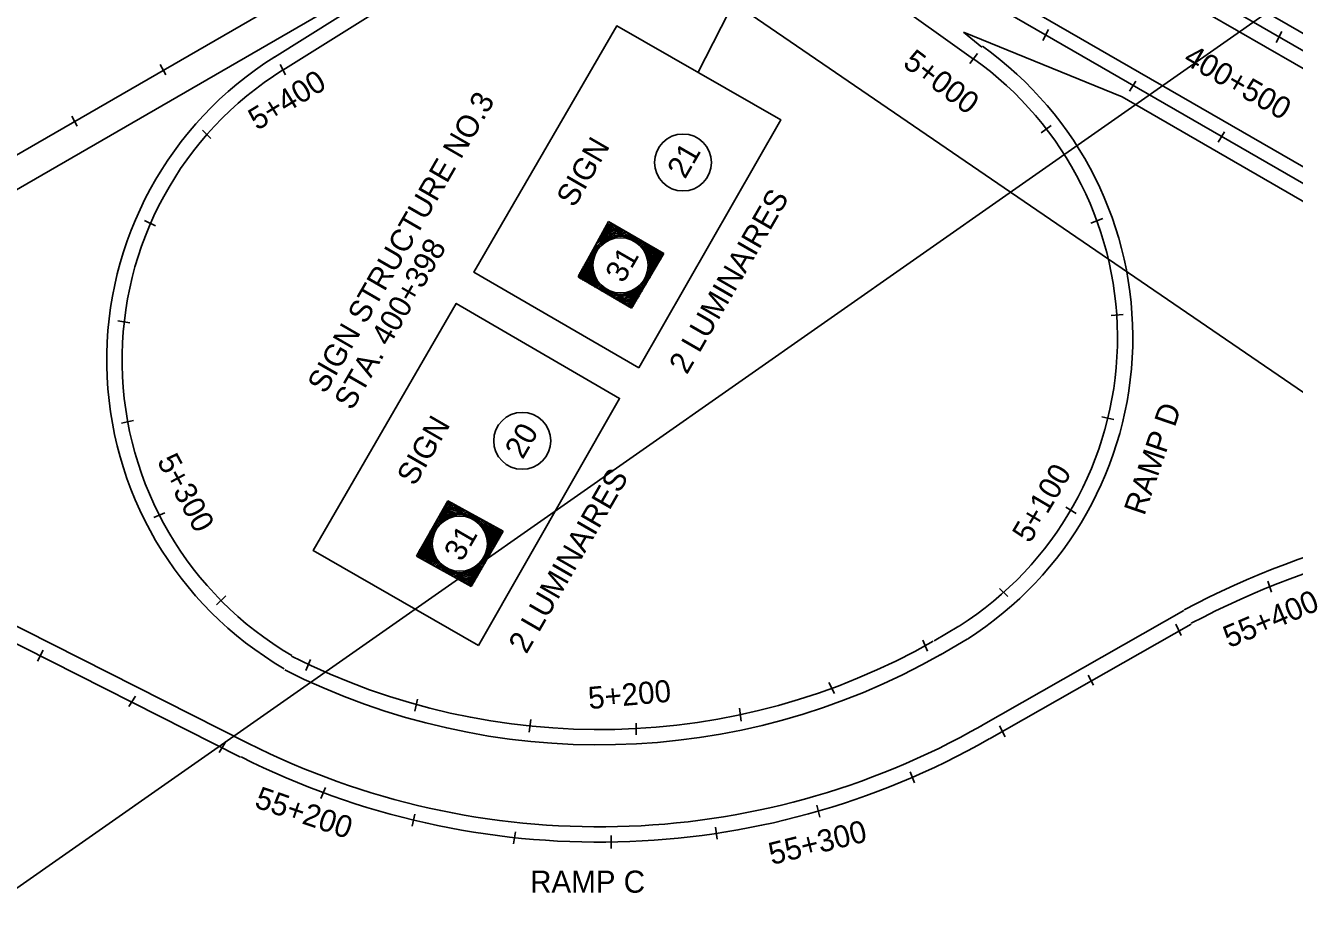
# Model space of a CAD drawing. Extents: x 36 to 2622, y -5330 to 219.
# Drawn here: x 2003.5 to 2175.5, y -4537.5 to -4415.8 of the extents above; entities that cross this region are included whole.
import ezdxf

# ---------------------------------------------------------------- set-up
doc = ezdxf.new("R2010")
doc.units = 0
doc.layers.add('2', color=7, linetype='Continuous')

msp = doc.modelspace()

# ---------------------------------------------------------------- linework, layer by layer
at = {"layer": '2'}
for p, q in [((2538.01, -4157.41), (1748.46, -4710.54)), ((1732.85, -4161.87), (2538.01, -4712.77)), ((1962.23, -4456.45), (2237.61, -4297.45)), ((2381.86, -4540.2), (2110.36, -4383.33)), ((2382.98, -4538.33), (2117.11, -4384.83)), ((2375.11, -4551.83), (2096.98, -4391.2)), ((2376.11, -4550.08), (2099.11, -4390.2)), ((2131.98, -4420.33), (2093.48, -4392.83)), ((2038.36, -4421.83), (2080.86, -4395.2)), ((2094.61, -4422.2), (2108.73, -4394.33)), ((2141.73, -4396.7), (2268.36, -4469.83)), ((1964.36, -4459.95), (2068.36, -4399.83)), ((2037.23, -4420.08), (2068.61, -4400.33)), ((2152.11, -4425.45), (2130.61, -4416.7)), ((2133.11, -4418.7), (2130.61, -4416.7)), ((2141.36, -4417.83), (2142.11, -4416.33)), ((2172.98, -4418.08), (2173.73, -4416.58)), ((2022.48, -4422.45), (2021.73, -4421.08)), ((2038.73, -4422.45), (2037.98, -4421.08)), ((2131.48, -4420.95), (2132.48, -4419.58)), ((2153.11, -4424.7), (2153.98, -4423.33)), ((2274.11, -4495.95), (2152.11, -4425.45)), ((2010.48, -4429.45), (2009.73, -4428.08)), ((2141.11, -4430.33), (2142.48, -4429.33)), ((2028.61, -4431.08), (2027.48, -4429.95)), ((2165.11, -4431.58), (2165.98, -4430.2)), ((2021.11, -4442.95), (2019.61, -4442.2)), ((2147.86, -4442.58), (2149.48, -4441.95)), ((2152.23, -4454.95), (2150.61, -4455.08)), ((2015.98, -4455.83), (2017.61, -4456.08)), ((2149.36, -4468.83), (2150.98, -4469.2)), ((2018.11, -4469.33), (2016.48, -4469.7)), ((2145.86, -4481.95), (2144.48, -4481.08)), ((2020.86, -4482.45), (2022.36, -4481.83)), ((2171.86, -4491.08), (2172.36, -4492.58)), ((2033.61, -4513.08), (1993.11, -4492.58)), ((2030.61, -4493.08), (2029.36, -4494.33)), ((2135.48, -4492.08), (2136.61, -4493.2)), ((2032.61, -4514.95), (1992.11, -4494.45)), ((2132.98, -4510.7), (2160.48, -4495.08)), ((2129.98, -4497.2), (2126.61, -4499.2)), ((2134.11, -4512.45), (2161.48, -4496.95)), ((2159.36, -4496.95), (2160.11, -4498.45)), ((2125.11, -4499.08), (2125.73, -4500.58)), ((2131.11, -4498.95), (2127.48, -4501.08)), ((2005.11, -4501.95), (2005.86, -4500.45)), ((2041.48, -4503.2), (2042.11, -4501.7)), ((2112.36, -4504.83), (2113.11, -4506.33)), ((2147.48, -4503.83), (2148.23, -4505.2)), ((2017.48, -4508.08), (2018.36, -4506.7)), ((2056.61, -4507.08), (2056.23, -4508.7)), ((2100.23, -4508.33), (2100.48, -4510.08)), ((2071.98, -4509.83), (2071.73, -4511.58)), ((2086.23, -4510.33), (2086.23, -4511.95)), ((2135.48, -4510.7), (2136.23, -4512.2)), ((2029.73, -4514.33), (2030.61, -4512.83)), ((2123.36, -4516.95), (2123.98, -4518.45)), ((2044.11, -4519.08), (2043.48, -4520.58)), ((2110.73, -4521.45), (2111.11, -4523.08)), ((2056.23, -4522.7), (2055.86, -4524.33)), ((2069.86, -4525.08), (2069.61, -4526.7)), ((2082.86, -4525.58), (2082.86, -4527.33)), ((2096.98, -4524.45), (2097.23, -4526.08))]:
    msp.add_line(p, q, dxfattribs=at)
for points in [[(2086.61, -4462.2), (2105.86, -4428.58), (2083.61, -4415.83), (2064.23, -4449.2)], [(2064.86, -4499.83), (2083.98, -4466.33), (2061.86, -4453.45), (2042.48, -4486.95)]]:
    msp.add_lwpolyline(points, close=True, dxfattribs=at)
for points in [[(2082.48, -4442.33), (2078.36, -4449.83)], [(2089.98, -4446.7), (2082.48, -4442.33)], [(2089.98, -4446.7), (2085.61, -4454.08)], [(2085.61, -4454.08), (2078.36, -4449.83)], [(2060.73, -4480.2), (2056.48, -4487.7)], [(2068.23, -4484.33), (2060.73, -4480.2)], [(2068.23, -4484.33), (2063.86, -4491.83)], [(2063.86, -4491.83), (2056.48, -4487.7)]]:
    msp.add_lwpolyline(points, dxfattribs=at)
for centre, radius in [((2092.58, -4434.35), 3.86), ((2084.12, -4448.29), 4.13), ((2084.12, -4448.29), 3.95), ((2084.12, -4448.29), 3.74), ((2070.79, -4472.08), 3.86), ((2062.33, -4486.02), 4.13), ((2062.33, -4486.02), 3.95), ((2062.33, -4486.02), 3.74)]:
    msp.add_circle(centre, radius, dxfattribs=at)
for centre, radius, start, end in [((2105.11, -4458.09), 48.44, 302.5087, 54.6076), ((2062.92, -4461.12), 48.44, 121.9999, 239.7607), ((2105.11, -4458.09), 46.36, 302.5087, 54.6076), ((2062.92, -4461.12), 46.36, 121.9999, 239.7607), ((2084.12, -4448.29), 4.89, 88.6036, 121.5088), ((2084.12, -4448.29), 5.06, 92.1022, 117.9954), ((2084.12, -4448.29), 5.26, 95.3377, 114.7487), ((2084.12, -4448.29), 5.45, 98.0414, 112.0368), ((2084.12, -4448.29), 5.62, 100.231, 109.8414), ((2084.12, -4448.29), 5.8, 102.2801, 107.7872), ((2084.12, -4448.29), 4.32, 66.9038, 143.621), ((2084.12, -4448.29), 4.53, 78.7747, 131.406), ((2084.12, -4448.29), 4.73, 84.969, 125.1626), ((2084.12, -4448.29), 4.32, 336.9038, 53.0962), ((2084.12, -4448.29), 4.32, 156.379, 233.621), ((2084.12, -4448.29), 4.53, 348.7747, 41.2253), ((2084.12, -4448.29), 4.73, 354.969, 35.031), ((2084.12, -4448.29), 4.89, 358.6036, 31.3964), ((2084.12, -4448.29), 5.06, 2.1022, 27.8978), ((2084.12, -4448.29), 5.26, 5.3377, 24.6623), ((2084.12, -4448.29), 5.45, 8.0414, 21.9586), ((2084.12, -4448.29), 5.62, 10.231, 19.769), ((2084.12, -4448.29), 5.8, 12.2801, 17.7199), ((2084.12, -4448.29), 5.06, 182.0046, 207.9954), ((2084.12, -4448.29), 4.89, 178.4912, 211.5088), ((2084.12, -4448.29), 4.73, 174.8374, 215.1626), ((2084.12, -4448.29), 4.53, 168.594, 221.406), ((2084.12, -4448.29), 5.8, 192.2128, 197.7872), ((2084.12, -4448.29), 5.62, 190.1586, 199.8414), ((2084.12, -4448.29), 5.45, 187.9632, 202.0368), ((2084.12, -4448.29), 5.26, 185.2513, 204.7486), ((2084.12, -4448.29), 4.32, 246.379, 323.0962), ((2084.12, -4448.29), 4.53, 258.594, 311.2253), ((2084.12, -4448.29), 4.73, 264.8374, 305.031), ((2084.12, -4448.29), 4.89, 268.4912, 301.3964), ((2084.12, -4448.29), 5.06, 272.0046, 297.8978), ((2084.12, -4448.29), 5.26, 275.2513, 294.6623), ((2084.12, -4448.29), 5.45, 277.9632, 291.9586), ((2084.12, -4448.29), 5.62, 280.1586, 289.769), ((2084.12, -4448.29), 5.8, 282.2128, 287.7199), ((2062.33, -4486.02), 4.73, 84.969, 125.1626), ((2062.33, -4486.02), 4.89, 88.6036, 121.5088), ((2062.33, -4486.02), 5.06, 92.1022, 117.9954), ((2062.33, -4486.02), 5.26, 95.3377, 114.7487), ((2062.33, -4486.02), 5.45, 98.0414, 112.0368), ((2062.33, -4486.02), 5.62, 100.231, 109.8414), ((2062.33, -4486.02), 5.8, 102.2801, 107.7872), ((2215.68, -4599.27), 117.99, 60.4381, 117.8815), ((2062.33, -4486.02), 4.32, 66.9038, 143.621), ((2062.33, -4486.02), 4.53, 78.7747, 131.406), ((2062.33, -4486.02), 4.32, 336.9038, 53.0962), ((2062.33, -4486.02), 4.53, 348.7747, 41.2253), ((2062.33, -4486.02), 4.32, 156.379, 233.621), ((2062.33, -4486.02), 4.73, 354.969, 35.031), ((2062.33, -4486.02), 4.89, 358.6036, 31.3964), ((2062.33, -4486.02), 5.06, 2.1022, 27.8978), ((2062.33, -4486.02), 5.26, 5.3377, 24.6623), ((2062.33, -4486.02), 5.45, 8.0414, 21.9586), ((2062.33, -4486.02), 5.62, 10.231, 19.769), ((2062.33, -4486.02), 5.8, 12.2801, 17.7199), ((2215.68, -4599.27), 115.91, 60.4381, 117.8802), ((2062.33, -4486.02), 5.06, 182.0046, 207.9954), ((2062.33, -4486.02), 4.89, 178.4912, 211.5088), ((2062.33, -4486.02), 4.73, 174.8374, 215.1626), ((2062.33, -4486.02), 4.53, 168.594, 221.406), ((2062.33, -4486.02), 5.8, 192.2128, 197.7872), ((2062.33, -4486.02), 5.62, 190.1586, 199.8414), ((2062.33, -4486.02), 5.45, 187.9632, 202.0368), ((2062.33, -4486.02), 5.26, 185.2513, 204.7486), ((2062.33, -4486.02), 4.32, 246.379, 323.0962), ((2062.33, -4486.02), 4.53, 258.594, 311.2253), ((2062.33, -4486.02), 4.73, 264.8374, 305.031), ((2062.33, -4486.02), 4.89, 268.4912, 301.3964), ((2062.33, -4486.02), 5.06, 272.0046, 297.8978), ((2062.33, -4486.02), 5.26, 275.2513, 294.6623), ((2062.33, -4486.02), 5.45, 277.9632, 291.9586), ((2062.33, -4486.02), 5.62, 280.1586, 289.769), ((2062.33, -4486.02), 5.8, 282.2128, 287.7199)]:
    msp.add_arc(centre, radius, start, end, dxfattribs=at)
for major_axis, ratio, start_param in [((58.78, -71.52), 0.992405, 5.130512), ((60.1, -73.12), 0.992572, 5.130512), ((67.15, -81.71), 0.993353, 5.130512), ((68.47, -83.31), 0.993481, 5.130466)]:
    msp.add_ellipse((2080.52, -4418.92), major_axis=major_axis, ratio=ratio, start_param=start_param, end_param=6.114022, dxfattribs=at)

# ---------------------------------------------------------------- texts
for s, height, rotation, p in [('5+000', 3, 322.9885, (2122.23, -4421.2)), ('400+500', 3, 330, (2160.23, -4420.83)), ('5+400', 3, 31.4262, (2034.86, -4430.08)), ('SIGN STRUCTURE NO.3', 2.9955, 60, (2044.11, -4465.83)), ('SIGN', 2.996, 60, (2077.86, -4440.58)), ('21', 2.996, 60, (2092.86, -4436.7)), ('2 LUMINAIRES', 2.9955, 60, (2093.11, -4463.2)), ('STA. 400+398', 2.9955, 60, (2047.73, -4468.08)), ('31', 2.996, 60, (2084.48, -4450.83)), ('RAMP D', 2.996, 71.0637, (2155.11, -4482.33)), ('SIGN', 2.996, 60, (2056.23, -4478.33)), ('20', 2.996, 60, (2070.86, -4474.7)), ('5+300', 3, 298.3014, (2021.23, -4474.83)), ('2 LUMINAIRES', 2.9955, 60, (2071.36, -4501.08)), ('5+100', 3, 59.4161, (2139.61, -4486.08)), ('31', 2.996, 60, (2062.61, -4488.58)), ('55+400', 3, 22.964, (2166.61, -4500.2)), ('5+200', 3, 5.252, (2079.86, -4508.45)), ('55+200', 3, 341.099, (2034.36, -4521.7)), ('55+300', 3, 13.9122, (2104.61, -4529.58))]:
    msp.add_text(s, height=height, rotation=rotation, dxfattribs=at).set_placement(p)
msp.add_text('RAMP C', height=2.996, dxfattribs=at).set_placement((2071.86, -4533.33))

doc.saveas('drawing.dxf')
